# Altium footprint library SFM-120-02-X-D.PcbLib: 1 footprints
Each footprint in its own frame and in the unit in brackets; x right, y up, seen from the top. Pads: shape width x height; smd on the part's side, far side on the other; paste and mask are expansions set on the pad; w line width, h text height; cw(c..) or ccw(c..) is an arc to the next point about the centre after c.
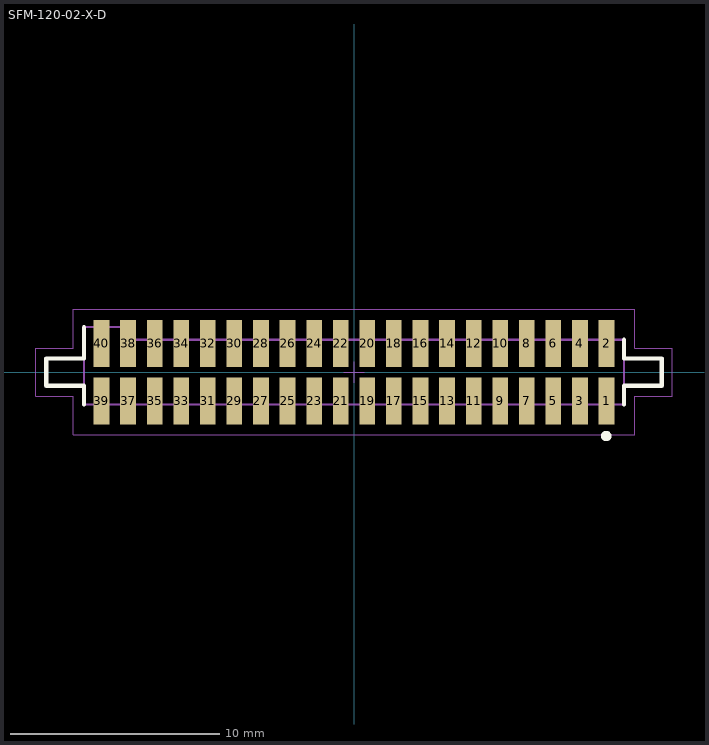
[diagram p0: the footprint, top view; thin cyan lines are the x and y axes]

## SFM-120-02-X-D [mm] "1.27mm pitch, 40 pin, socket strip; SMT"
height 4.57
pads (40):
  rect 0.75x2.25 smd mask+0: 1(12.065,-1.375) 2(12.065,1.375) 3(10.795,-1.375) 4(10.795,1.375) 5(9.525,-1.375) 6(9.525,1.375) 7(8.255,-1.375) 8(8.255,1.375) 9(6.985,-1.375) 10(6.985,1.375) 11(5.715,-1.375) 12(5.715,1.375) 13(4.445,-1.375) 14(4.445,1.375) 15(3.175,-1.375) 16(3.175,1.375) 17(1.905,-1.375) 18(1.905,1.375) 19(0.635,-1.375) 20(0.635,1.375) 21(-0.635,-1.375) 22(-0.635,1.375) 23(-1.905,-1.375) 24(-1.905,1.375) 25(-3.175,-1.375) 26(-3.175,1.375) 27(-4.445,-1.375) 28(-4.445,1.375) 29(-5.715,-1.375) 30(-5.715,1.375) 31(-6.985,-1.375) 32(-6.985,1.375) 33(-8.255,-1.375) 34(-8.255,1.375) 35(-9.525,-1.375) 36(-9.525,1.375) 37(-10.795,-1.375) 38(-10.795,1.375) 39(-12.065,-1.375) 40(-12.065,1.375)
Top Overlay:
  circle w0.25: c12.05,-3.05 r0.125
  lines w0.2: -12.9,-1.55 -12.9,-0.65 -14.7,-0.65 -14.7,0.65 -12.9,0.65 -12.9,2.15 ; 12.9,-1.55 12.9,-0.65 14.7,-0.65 14.7,0.65 12.9,0.65 12.9,1.55
Mechanical 12:
  lines w0.001: -14.7,-0.65 -14.7,0.65 -12.9,0.65 -12.9,2.15 -10.85,2.15 -10.85,1.55 12.9,1.55 12.9,0.65 14.7,0.65 14.7,-0.65 12.9,-0.65 12.9,-1.55 -12.9,-1.55 -12.9,-0.65 -14.7,-0.65
Mechanical 13:
  lines w0.1: -12.9,-0.65 -14.7,-0.65 -14.7,0.65 -12.9,0.65 ; -12.9,-0.65 -12.9,-1.55 12.9,-1.55 12.9,-0.65 ; -12.9,-0.65 -12.9,0.65 ; -12.9,0.65 -12.9,2.15 -10.85,2.15 -10.85,1.55 12.9,1.55 12.9,0.65 ; 12.9,-0.65 14.7,-0.65 14.7,0.65 12.9,0.65 ; 12.9,-0.65 12.9,0.65
  text ".Designator" at 0,-0.127 h1.52
Mechanical 15:
  lines w0.05: -0.5,0 0.5,0 ; 0,-0.5 0,0.5 ; -15.2,-1.15 -13.4,-1.15 -13.4,-3 13.4,-3 13.4,-1.15 15.2,-1.15 15.2,1.15 13.4,1.15 13.4,3 -13.4,3 -13.4,1.15 -15.2,1.15 -15.2,-1.15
